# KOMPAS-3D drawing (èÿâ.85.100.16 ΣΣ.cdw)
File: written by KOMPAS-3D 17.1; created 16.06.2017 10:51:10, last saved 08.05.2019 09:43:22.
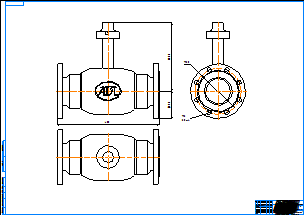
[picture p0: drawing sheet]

Sheet 1: A0, landscape

Title block, sheet 1: name: КШГ.85.100.16 фф; material: Внимание! Данный продукт является объектом авторского права ООО «Торговый Дом АДЛ». / Запрещается изменение, копирование, распространение / (в том числе путем копирования на другие сайты и ресурсы в Интернете) / или любое иное использование информации и объектов без предварительного / согласия правообладателя (ООО «Торговый Дом АДЛ»).; scale: 1:1; sheets: 1; organisation: ООО "Торговый дом АДЛ"; sheet format: A0; stored path: C:\Users\tra\Desktop\2д чертежи\Шаровые краны БИВАЛ\КШ_Бивал_серия_82_85\KOMPAS 2D\КШГ.85.100.16 фф.cdw

Views: Спереди 1, Проекционный вид 2, Проекционный вид 3
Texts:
  Klimkovich
  ADL
Dimensions and other numbers on the sheet: 400; 266,9; 107,5; 180; 18; 8 Отв.; 1:1; 1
